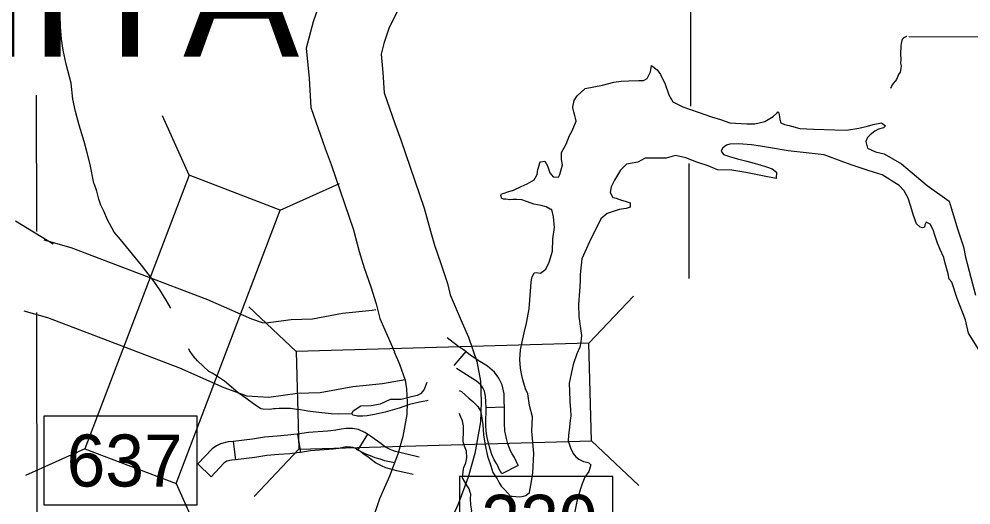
# Model space of a CAD drawing. Extents: x -492261 to -432772, y 1441225 to 1452922.
# Drawn here: x -463644.7 to -463423.9, y 1451354.7 to 1451467.4 of the extents above; entities that cross this region are included whole.
import ezdxf

# ---------------------------------------------------------------- set-up
doc = ezdxf.new("R2010")
doc.units = 0
doc.layers.add('Default', color=7, linetype='Continuous')

msp = doc.modelspace()

# ---------------------------------------------------------------- linework, layer by layer
at = {"layer": 'Default'}
for p, q in [((-463605.24, 1451431.14), (-463611.42, 1451444.9)), ((-463584.09, 1451423.09), (-463570.32, 1451429.27)), ((-463512.56, 1451392.19), (-463502.19, 1451403.15)), ((-463580.41, 1451390.27), (-463591.38, 1451400.64)), ((-463541.1, 1451390.29), (-463543.84, 1451387)), ((-463532.11, 1451377.41), (-463536.39, 1451377.21)), ((-463580.1, 1451371.13), (-463579.4, 1451366.9)), ((-463563.84, 1451371.11), (-463566.09, 1451367.47)), ((-463594.98, 1451369.45), (-463594.49, 1451365.19)), ((-463511.92, 1451369.57), (-463500.95, 1451359.21)), ((-463629.37, 1451367.69), (-463643.13, 1451361.51)), ((-463579.78, 1451367.65), (-463590.14, 1451356.69)), ((-463603.24, 1451364.2), (-463600.12, 1451361.26)), ((-463528.93, 1451363.88), (-463532.75, 1451361.93)), ((-463608.22, 1451359.64), (-463602.04, 1451345.88))]:
    msp.add_line(p, q, dxfattribs=at)
for points in [[(-463489.38, 1451648.59), (-463489.44, 1451641.74), (-463488.97, 1451490.05), (-463489, 1451447.14)], [(-463574.79, 1451471.63), (-463576.47, 1451466.71), (-463578.1, 1451460.62), (-463577.39, 1451453.58), (-463576.99, 1451446.84), (-463573.67, 1451437.35), (-463572.32, 1451433.66), (-463567.14, 1451418.5), (-463565.76, 1451413.48), (-463564.65, 1451409.69), (-463563.08, 1451405.25), (-463561.84, 1451401.35), (-463561, 1451397.97), (-463557.64, 1451390.18)], [(-463556.62, 1451469.91), (-463558.89, 1451465.15), (-463560.06, 1451461.72), (-463560.73, 1451459.22), (-463560.3, 1451454.94), (-463560.02, 1451450.24), (-463557.54, 1451443.14), (-463556.16, 1451439.39), (-463550.74, 1451423.54), (-463549.27, 1451418.15), (-463548.33, 1451414.97), (-463546.83, 1451410.71), (-463545.34, 1451406.03), (-463544.7, 1451403.46), (-463541.9, 1451396.95)], [(-463609.46, 1451400.36), (-463610.58, 1451402.22), (-463612.03, 1451404.55), (-463613.42, 1451406.59), (-463615.27, 1451408.97), (-463616.26, 1451410.28), (-463621.11, 1451416.23), (-463622.61, 1451417.93), (-463624.24, 1451421), (-463624.94, 1451422.65), (-463625.7, 1451424.19), (-463626.17, 1451425.61), (-463626.65, 1451427.49), (-463627.18, 1451429.03), (-463627.35, 1451429.32), (-463628.19, 1451433.65), (-463628.85, 1451436.34), (-463629.56, 1451438.96), (-463630.74, 1451442.78), (-463631.57, 1451445.92), (-463632.17, 1451448.83), (-463632.61, 1451452.48), (-463633.74, 1451456.88), (-463634.4, 1451460.13), (-463634.83, 1451462.7), (-463635.08, 1451465.56), (-463635.11, 1451468.13)], [(-463438.81, 1451463.32), (-463438.93, 1451463.3), (-463439.06, 1451463.24), (-463439.18, 1451463.18), (-463439.38, 1451463.07), (-463439.58, 1451462.91), (-463439.79, 1451462.69), (-463439.89, 1451462.59), (-463439.99, 1451462.39), (-463440.12, 1451461.72), (-463440.21, 1451461.05), (-463440.29, 1451459.32), (-463440.22, 1451457.99), (-463440.26, 1451457.17), (-463440.16, 1451456.55), (-463440.2, 1451455.88), (-463440.38, 1451455.02), (-463440.71, 1451454.49), (-463441.22, 1451453.38), (-463442.2, 1451452.08), (-463442.57, 1451451.26)], [(-463438.33, 1451463.32), (-463413.23, 1451463.26), (-463408.67, 1451463.2), (-463385.42, 1451463.24)], [(-463523.73, 1451408.43), (-463522.48, 1451409.4), (-463521.73, 1451411), (-463520.99, 1451413.52), (-463520.93, 1451416.38), (-463520.53, 1451419.01), (-463520.76, 1451421.53), (-463521.15, 1451423.19), (-463521.5, 1451423.3), (-463522.47, 1451423.82), (-463523.61, 1451424.1), (-463525.32, 1451424.45), (-463526.8, 1451424.96), (-463528.06, 1451425.42), (-463529.26, 1451425.53), (-463530.17, 1451425.53), (-463530.97, 1451425.48), (-463531.77, 1451425.59), (-463531.94, 1451425.59), (-463532.34, 1451425.59), (-463532.8, 1451425.82), (-463532.91, 1451426.28), (-463532.97, 1451426.56), (-463532.79, 1451426.85), (-463532.17, 1451427.02), (-463531.31, 1451427.31), (-463530.05, 1451427.71), (-463528.23, 1451428.56), (-463526.86, 1451429.14), (-463525.26, 1451430.11), (-463524.52, 1451431.31), (-463524.34, 1451432.45), (-463524.17, 1451433.2), (-463523.94, 1451434), (-463523.77, 1451434.28), (-463522.74, 1451434.4), (-463522.17, 1451433.37), (-463521.6, 1451431.71), (-463520.81, 1451430.79), (-463519.61, 1451430.74), (-463519.27, 1451431.36), (-463518.64, 1451433.6), (-463518.86, 1451434.8), (-463518.86, 1451436.4), (-463517.83, 1451438.34), (-463517.03, 1451440.4), (-463516.4, 1451441.43), (-463515.49, 1451443.66), (-463515.66, 1451444.41), (-463515.83, 1451444.98), (-463516.06, 1451445.84), (-463516.17, 1451446.47), (-463516.23, 1451446.64), (-463516.23, 1451447.04), (-463515.94, 1451448.52), (-463515.26, 1451449.55), (-463513.37, 1451451.27), (-463509.38, 1451452.01), (-463506.75, 1451452.7), (-463505.04, 1451452.93), (-463503.27, 1451453.04), (-463500.99, 1451453.15), (-463499.9, 1451453.1), (-463499.04, 1451453.61), (-463498.24, 1451455.1), (-463498.02, 1451456.58), (-463496.7, 1451455.61), (-463495.9, 1451454.53), (-463494.82, 1451452.29), (-463494.02, 1451449.83), (-463493.11, 1451448.18), (-463490.77, 1451447.03), (-463487.18, 1451445.77), (-463484.1, 1451444.68), (-463482.04, 1451444.05), (-463479.82, 1451443.31), (-463475.88, 1451443.08), (-463474.05, 1451443.08), (-463471.77, 1451443.59), (-463469.83, 1451444.74), (-463468.97, 1451445.54), (-463468.69, 1451445.88), (-463468.46, 1451445.59), (-463468.34, 1451444.68), (-463468.29, 1451444.11), (-463468.06, 1451443.31), (-463467.2, 1451442.91), (-463466.06, 1451442.68), (-463463.61, 1451441.99), (-463460.36, 1451441.82), (-463455.51, 1451441.7), (-463452.77, 1451441.64), (-463449.97, 1451442.1), (-463447.97, 1451442.56), (-463446.66, 1451442.9), (-463444.72, 1451443.3), (-463443.8, 1451442.61), (-463444.26, 1451442.16), (-463445.35, 1451441.81), (-463446.2, 1451441.36), (-463447.34, 1451440.56)], [(-463640.67, 1451449.73), (-463640.63, 1451418.11)], [(-463447.34, 1451440.56), (-463447.92, 1451439.87), (-463448.32, 1451439.01), (-463447.97, 1451437.41), (-463446.09, 1451436.55), (-463444.09, 1451436.09), (-463440.04, 1451433.8), (-463436.56, 1451430.83), (-463434.11, 1451428.77), (-463429.03, 1451425.16), (-463428.52, 1451423.56), (-463426.98, 1451418.53), (-463425.67, 1451414.52), (-463425.22, 1451412.18), (-463423.97, 1451407.43), (-463422.89, 1451403.37)], [(-463432.69, 1451418.47), (-463433.38, 1451419.79), (-463434.35, 1451420.25), (-463434.63, 1451419.62), (-463434.69, 1451419.1), (-463435.15, 1451418.93), (-463435.72, 1451419.1), (-463436.57, 1451419.9), (-463437.26, 1451421.85), (-463437.88, 1451423.91), (-463438.51, 1451425.85), (-463439.42, 1451427.57), (-463440.62, 1451428.77), (-463444.5, 1451431.23), (-463447.52, 1451432.15), (-463451.74, 1451433.58), (-463453.46, 1451434.15), (-463458.02, 1451435.92), (-463462.19, 1451436.33), (-463466.3, 1451436.84), (-463470.86, 1451437.59), (-463472.74, 1451437.93), (-463474.8, 1451438.22), (-463477.88, 1451438.45), (-463479.82, 1451438.39), (-463480.62, 1451438.16), (-463481.48, 1451437.48), (-463481.76, 1451436.96), (-463481.88, 1451436.73), (-463481.36, 1451435.93), (-463479.94, 1451435.47), (-463478.11, 1451434.96), (-463475.89, 1451434.38), (-463472.86, 1451433.58), (-463471.32, 1451433.07), (-463470.07, 1451432.67), (-463469.04, 1451431.87), (-463469.1, 1451430.38), (-463472.29, 1451431.01), (-463476.12, 1451431.75), (-463479.37, 1451432.33), (-463482.68, 1451432.44), (-463484.9, 1451433.36), (-463487.47, 1451434.16), (-463490.04, 1451435.19), (-463492.44, 1451435.71), (-463494.61, 1451435.13), (-463497.35, 1451435.13), (-463499.46, 1451435.13), (-463501.17, 1451434.22), (-463503.8, 1451433.71), (-463505.22, 1451432.33), (-463506.6, 1451429.99), (-463507.34, 1451428.44), (-463507.62, 1451427.13), (-463507, 1451425.98), (-463506.2, 1451425.81), (-463505, 1451425.35), (-463504.09, 1451425.18), (-463502.95, 1451424.78), (-463503, 1451423.75), (-463503.92, 1451423.47), (-463505.52, 1451423.18), (-463506.94, 1451422.72), (-463508.26, 1451422.27), (-463509.8, 1451421.01), (-463512.37, 1451415.69), (-463514.14, 1451411.74), (-463514.54, 1451408.14), (-463514.55, 1451406.6), (-463514.72, 1451404.25), (-463514.95, 1451401.22), (-463514.84, 1451398.42), (-463514.5, 1451395.61), (-463514.21, 1451394.01), (-463514.44, 1451392.52), (-463514.61, 1451391.32), (-463515.36, 1451389.72), (-463516.16, 1451387.26), (-463517.07, 1451382.91), (-463516.96, 1451379.03), (-463516.96, 1451378.68), (-463516.79, 1451376.74), (-463516.74, 1451375.36), (-463516.97, 1451373.65), (-463517.02, 1451372.68), (-463517.25, 1451370.85), (-463517.31, 1451369.59), (-463517.14, 1451368.9), (-463516.8, 1451367.93), (-463516.17, 1451366.61), (-463515.6, 1451365.87), (-463514.86, 1451365.35), (-463513.78, 1451364.78), (-463512.98, 1451364.61), (-463512.52, 1451364.44), (-463512.06, 1451363.98), (-463512.52, 1451362.49), (-463513.44, 1451361.12), (-463514.07, 1451359.58), (-463515.21, 1451356.26)], [(-463489.36, 1451433.87), (-463489.34, 1451407.18)], [(-463645.45, 1451420.59), (-463636.76, 1451415.25)], [(-463422.04, 1451390.61), (-463424.55, 1451394.5), (-463425.23, 1451397.59), (-463427.11, 1451402.57), (-463428.36, 1451406.34), (-463428.99, 1451407.09), (-463429.27, 1451408.29), (-463429.9, 1451410.75), (-463430.24, 1451412.06), (-463431.1, 1451413.95), (-463431.72, 1451415.38), (-463432.29, 1451417.27), (-463432.69, 1451418.47)], [(-463638.92, 1451416.19), (-463632.68, 1451414.43), (-463600.97, 1451402.37), (-463590.74, 1451397.86), (-463588.3, 1451396.97), (-463587.43, 1451396.92), (-463581.55, 1451397.72), (-463576.65, 1451397.88), (-463569.68, 1451399.15), (-463562.81, 1451399.83), (-463561.97, 1451399.99)], [(-463542.59, 1451381.23), (-463542.07, 1451380.98), (-463540.36, 1451379.49), (-463539.45, 1451378.69), (-463538.25, 1451377.54), (-463537.63, 1451376.51), (-463537.45, 1451375.37), (-463537.11, 1451373.31), (-463537, 1451370.96), (-463536.6, 1451368.56), (-463536.03, 1451365.99), (-463535.29, 1451363.81), (-463534.84, 1451362.21), (-463533.81, 1451360.78), (-463533.36, 1451359.87), (-463532.84, 1451359.07), (-463532.1, 1451358.26), (-463531.3, 1451357.46), (-463530.68, 1451356.78), (-463530.33, 1451356.72), (-463529.48, 1451356.66), (-463528.56, 1451356.55), (-463527.71, 1451356.78), (-463527.14, 1451356.89), (-463526.34, 1451357.63), (-463525.82, 1451360.15), (-463525.54, 1451362.15), (-463525.3, 1451366.61), (-463525.76, 1451371.82), (-463525.58, 1451375.14), (-463526.32, 1451377.77), (-463526.72, 1451380.46), (-463527.23, 1451381.6), (-463527.86, 1451383.72), (-463528.09, 1451384.75), (-463528.37, 1451386.41), (-463528.54, 1451388.41), (-463528.43, 1451390.7), (-463527.97, 1451392.53), (-463527.51, 1451394.59), (-463526.99, 1451396.87), (-463526.42, 1451400.19), (-463526.08, 1451404.31), (-463525.9, 1451406.37), (-463525.73, 1451407.4), (-463525.22, 1451408.54), (-463524.76, 1451408.6), (-463523.73, 1451408.43)], [(-463643.58, 1451399.7), (-463638.07, 1451398.14), (-463607.47, 1451386.5), (-463597.16, 1451381.96), (-463591.84, 1451380), (-463586.77, 1451379.71), (-463580.1, 1451380.61), (-463574.83, 1451380.79), (-463567.3, 1451382.16), (-463560.37, 1451382.84), (-463555.14, 1451383.83)], [(-463640.61, 1451399.34), (-463640.55, 1451347.77), (-463642.18, 1451255.17)], [(-463541.88, 1451396.91), (-463540.46, 1451393.57), (-463538.49, 1451387.96), (-463537.69, 1451383.38), (-463537.55, 1451378.63), (-463537.63, 1451373.94), (-463538.98, 1451366.66), (-463540.56, 1451361.14), (-463542.88, 1451354.91), (-463545.11, 1451349.91)], [(-463541.1, 1451390.29), (-463541.59, 1451390.69), (-463543.01, 1451391.62), (-463545.39, 1451393.42)], [(-463567.53, 1451375.84), (-463570.67, 1451375.78), (-463572.27, 1451375.82), (-463575.81, 1451376.24), (-463577.69, 1451376.44), (-463579.41, 1451376.77), (-463580.26, 1451376.87), (-463581.69, 1451377.03), (-463583.12, 1451377.07), (-463584.37, 1451377.06), (-463585.28, 1451376.99), (-463585.57, 1451376.98), (-463586.54, 1451376.86), (-463588.08, 1451376.9), (-463588.59, 1451377.01), (-463590.26, 1451378.13), (-463592.1, 1451379.43), (-463593.88, 1451380.72), (-463596.99, 1451383.38), (-463598.88, 1451384.67), (-463599.91, 1451385.23), (-463600.66, 1451385.68), (-463603.25, 1451388.11), (-463604.29, 1451389.3), (-463605.1, 1451390.55), (-463605.31, 1451390.89)], [(-463557.66, 1451390.22), (-463556.46, 1451387.37), (-463555.13, 1451383.61), (-463554.79, 1451381.66), (-463554.7, 1451378.52), (-463554.75, 1451375.66), (-463555.69, 1451370.59), (-463556.85, 1451366.5), (-463558.76, 1451361.4), (-463561.11, 1451356.11), (-463563.01, 1451350.4)], [(-463532.11, 1451377.41), (-463532.17, 1451378.71), (-463532.19, 1451380.44), (-463532.65, 1451382.58), (-463533.44, 1451384.12), (-463534.44, 1451385.48), (-463536.07, 1451386.87), (-463537.81, 1451387.96), (-463538.91, 1451388.67), (-463540.41, 1451389.71), (-463541.1, 1451390.29)], [(-463536.39, 1451377.21), (-463536.46, 1451378.59), (-463536.47, 1451379.96), (-463536.72, 1451381.12), (-463537.1, 1451381.86), (-463537.6, 1451382.54), (-463538.62, 1451383.41), (-463540.1, 1451384.34), (-463543.21, 1451386.32)], [(-463549.79, 1451378.89), (-463550.12, 1451378.81), (-463551.84, 1451378.52), (-463554.12, 1451378.01), (-463556.52, 1451377.15), (-463559.77, 1451376.23), (-463561.83, 1451375.78), (-463563.94, 1451375.38), (-463564.96, 1451375.26), (-463566.16, 1451375.26), (-463567.19, 1451375.55), (-463567.53, 1451375.84), (-463567.19, 1451376.52), (-463565.42, 1451377.72), (-463563.02, 1451377.78), (-463560.85, 1451378.18), (-463558.51, 1451379.21), (-463556.06, 1451379.26), (-463553.38, 1451379.89), (-463552.29, 1451380.18), (-463551.32, 1451380.64), (-463550.69, 1451381.38), (-463550.03, 1451383.14)], [(-463532.75, 1451361.93), (-463533.3, 1451363.01), (-463533.62, 1451363.74), (-463533.95, 1451364.29), (-463534.5, 1451365.17), (-463535.01, 1451366.44), (-463535.4, 1451367.64), (-463535.78, 1451369.02), (-463536.1, 1451370.33), (-463536.25, 1451371.23), (-463536.32, 1451372.01), (-463536.4, 1451372.95), (-463536.4, 1451373.71), (-463536.41, 1451374.61), (-463536.37, 1451376.15), (-463536.38, 1451376.99), (-463536.39, 1451377.21)], [(-463528.93, 1451363.88), (-463529.43, 1451364.85), (-463529.81, 1451365.71), (-463530.29, 1451366.52), (-463530.67, 1451367.12), (-463530.98, 1451367.9), (-463531.3, 1451368.86), (-463531.63, 1451370.1), (-463531.9, 1451371.19), (-463532, 1451371.78), (-463532.05, 1451372.37), (-463532.11, 1451373.14), (-463532.12, 1451373.76), (-463532.13, 1451374.57), (-463532.09, 1451376.12), (-463532.1, 1451377.11), (-463532.11, 1451377.41)], [(-463638.94, 1451354.73), (-463603.37, 1451354.73), (-463603.37, 1451375.28), (-463638.94, 1451375.28), (-463638.94, 1451354.73)], [(-463541.61, 1451363.05), (-463541.52, 1451363.36), (-463541.06, 1451364.5), (-463540.83, 1451365.65), (-463540.89, 1451367.19), (-463541.34, 1451368.33), (-463541.68, 1451369.31), (-463541.57, 1451372.05), (-463541.57, 1451373.08), (-463541.85, 1451374.23), (-463542.36, 1451375.43), (-463542.55, 1451375.92)], [(-463580.1, 1451371.13), (-463580.25, 1451371.1), (-463582.33, 1451370.86), (-463584.81, 1451370.66), (-463587.74, 1451370.39), (-463590.55, 1451369.96), (-463594.98, 1451369.45)], [(-463563.84, 1451371.11), (-463564.46, 1451371.49), (-463565.94, 1451372.18), (-463567.38, 1451372.4), (-463568.85, 1451372.46), (-463569.94, 1451372.3), (-463571.2, 1451372.06), (-463572.33, 1451371.89), (-463573.15, 1451371.83), (-463577.58, 1451371.54), (-463580.1, 1451371.13)], [(-463551.85, 1451365.8), (-463556.07, 1451366.81), (-463557.35, 1451367.13), (-463558.1, 1451367.34), (-463558.75, 1451367.66), (-463559.72, 1451368.1), (-463560.36, 1451368.65), (-463561.3, 1451369.32), (-463562.3, 1451370.03), (-463563.16, 1451370.69), (-463563.84, 1451371.11)], [(-463594.98, 1451369.45), (-463596.18, 1451369.31), (-463597.98, 1451368.86), (-463598.85, 1451368.41), (-463599.89, 1451367.75), (-463603.24, 1451364.2)], [(-463566.09, 1451367.47), (-463566.49, 1451367.71), (-463567.19, 1451368.03), (-463567.8, 1451368.13), (-463568.62, 1451368.16), (-463569.23, 1451368.07), (-463570.48, 1451367.83), (-463571.85, 1451367.63), (-463572.86, 1451367.55), (-463577.09, 1451367.28), (-463579.4, 1451366.9)], [(-463579.4, 1451366.9), (-463579.66, 1451366.86), (-463581.91, 1451366.59), (-463584.44, 1451366.39), (-463587.21, 1451366.14), (-463589.98, 1451365.71), (-463594.49, 1451365.19)], [(-463553.3, 1451361.74), (-463557.09, 1451362.65), (-463558.45, 1451362.98), (-463559.64, 1451363.32), (-463560.59, 1451363.79), (-463562.04, 1451364.46), (-463563, 1451365.26), (-463563.79, 1451365.83), (-463564.85, 1451366.58), (-463565.6, 1451367.16), (-463566.09, 1451367.47)], [(-463594.49, 1451365.19), (-463595.4, 1451365.09), (-463596.45, 1451364.82), (-463596.71, 1451364.69), (-463597.14, 1451364.42), (-463600.12, 1451361.26)], [(-463547.91, 1451350.39), (-463544.46, 1451351.08), (-463542.38, 1451351.12), (-463541.35, 1451351.29), (-463540.84, 1451351.46), (-463540.33, 1451352.09), (-463539.7, 1451353.35), (-463539.87, 1451354.72), (-463539.98, 1451356.15), (-463539.92, 1451357.24), (-463540.04, 1451357.58), (-463540.26, 1451358.44), (-463540.72, 1451359.13), (-463541.82, 1451361.03), (-463541.61, 1451363.05)], [(-463542.54, 1451340.76), (-463506.97, 1451340.76), (-463506.97, 1451361.31), (-463542.54, 1451361.31), (-463542.54, 1451340.76)], [(-463515.21, 1451356.26), (-463515.9, 1451352.77)]]:
    msp.add_lwpolyline(points, dxfattribs=at)
for points in [[(-463605.24, 1451431.14), (-463629.37, 1451367.69), (-463608.22, 1451359.64), (-463584.09, 1451423.09)], [(-463512.56, 1451392.19), (-463580.41, 1451390.27), (-463579.78, 1451367.65), (-463511.92, 1451369.57)], [(-463638.94, 1451354.73), (-463603.37, 1451354.73), (-463603.37, 1451375.28), (-463638.94, 1451375.28)], [(-463542.54, 1451340.76), (-463506.97, 1451340.76), (-463506.97, 1451361.31), (-463542.54, 1451361.31)]]:
    msp.add_lwpolyline(points, close=True, dxfattribs=at)
msp.add_arc((-463551.82, 1451395.41), 31.43, 242.2154, 259.387, dxfattribs=at)

# ---------------------------------------------------------------- texts
for s, height, p in [('WASHITA', 30.171, (-463763.5, 1451458.66)), ('637', 12.057, (-463633.63, 1451358.98)), ('320', 12.057, (-463537.45, 1451345.01))]:
    msp.add_text(s, height=height, dxfattribs=at).set_placement(p)

doc.saveas('drawing.dxf')
